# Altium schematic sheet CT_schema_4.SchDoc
size 357 x 184 mm
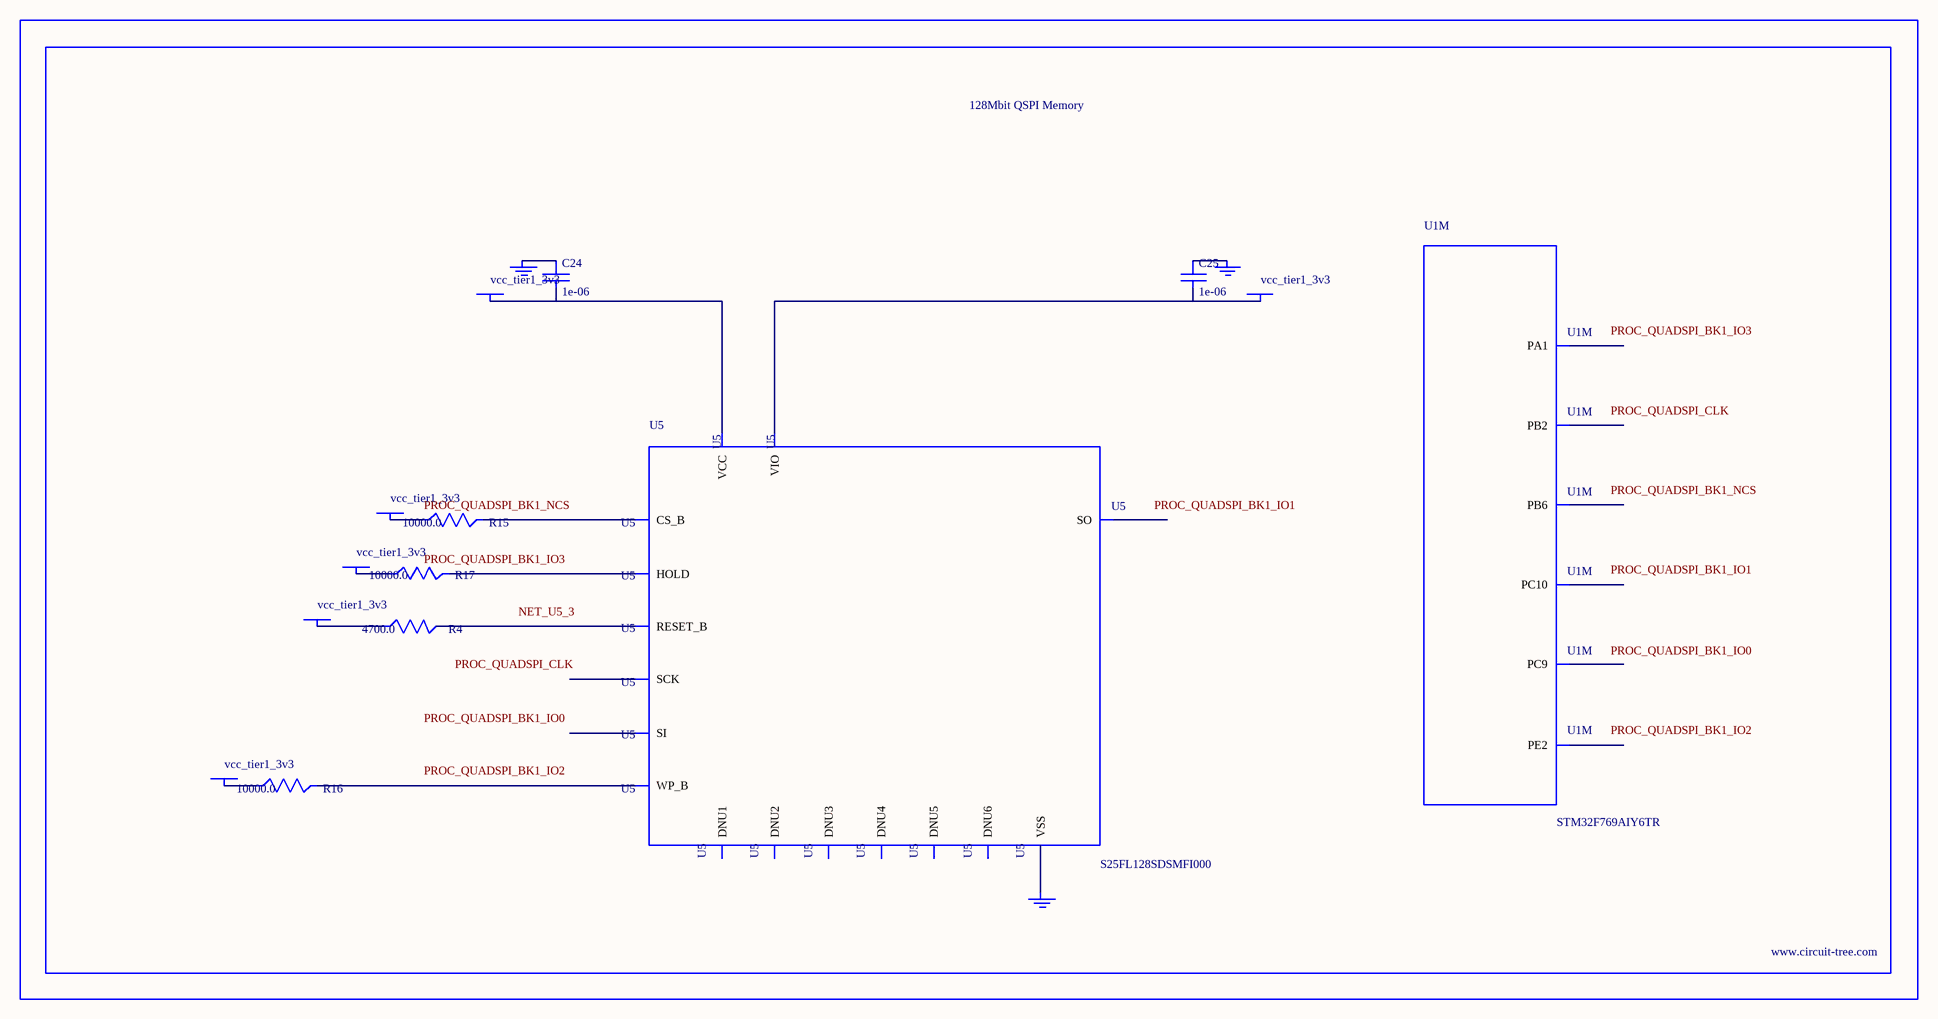
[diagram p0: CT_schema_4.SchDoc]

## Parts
BORDER3  (no value)
C24  1e-06  [C0603]
C25  1e-06  [C0603]
GND_INSTANCE_3_0  (no value)
GND_INSTANCE_3_1  (no value)
GND_INSTANCE_3_2  (no value)
POWER_INSTANCE_3_0  vcc_tier1_3v3
POWER_INSTANCE_3_1  vcc_tier1_3v3
POWER_INSTANCE_3_2  vcc_tier1_3v3
POWER_INSTANCE_3_3  vcc_tier1_3v3
POWER_INSTANCE_3_4  vcc_tier1_3v3
POWER_INSTANCE_3_5  vcc_tier1_3v3
R4  4700.0  [R0603]
R15  10000.0  [R0603]
R16  10000.0  [R0603]
R17  10000.0  [R0603]
U1  STM32F769AIY6TR  [WLCSP180]  (part M of 15)
U5  S25FL128SDSMFI000  [S25FL128SDSMFI000]

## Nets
NetC24_1: C24.1 GND_INSTANCE_3_0.0(GND)
NetC24_2: C24.2 POWER_INSTANCE_3_1.0(PWR) U5.2(VCC)
NetC25_1: C25.1 GND_INSTANCE_3_1.0(GND)
NetC25_2: C25.2 POWER_INSTANCE_3_4.0(PWR) U5.14(VIO)
NetGND_INSTANCE_3_2_0: GND_INSTANCE_3_2.0(GND) U5.10(VSS)
NetPOWER_INSTANCE_3_0_0: POWER_INSTANCE_3_0.0(PWR) R17.1
NetPOWER_INSTANCE_3_2_0: POWER_INSTANCE_3_2.0(PWR) R15.1
NetPOWER_INSTANCE_3_3_0: POWER_INSTANCE_3_3.0(PWR) R16.1
NetPOWER_INSTANCE_3_5_0: POWER_INSTANCE_3_5.0(PWR) R4.1
NetR4_2: R4.2 U5.3(RESET_B)
NetR15_2: R15.2 U5.7(CS_B)
NetR16_2: R16.2 U5.9(WP_B)
NetR17_2: R17.2 U5.1(HOLD)

Not connected (* = marked no-connect by the designer): U1 B4(PC10) B9(PB6) E1(PC9) E10(PE2) J7(PB2) J11(PA1); U5 4(DNU1) 5(DNU2) 6(DNU6) 8(SO) 11(DNU3) 12(DNU4) 13(DNU5) 15(SI) 16(SCK)

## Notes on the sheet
- Labels drawn without touching a wire or pin: NET_U5_3, PROC_QUADSPI_BK1_IO0, PROC_QUADSPI_BK1_IO1, PROC_QUADSPI_BK1_IO2, PROC_QUADSPI_BK1_IO3, PROC_QUADSPI_BK1_NCS, PROC_QUADSPI_CLK

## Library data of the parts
BORDER3 = BORDER_PAGE3
C24 C25 = C0603C105K3RACTU
GND_INSTANCE_3_0-GND_INSTANCE_3_2 = GND
POWER_INSTANCE_3_0-POWER_INSTANCE_3_5 = PWR
R4 = RC0603JR-074K7L
R15-R17 = RC0603JR-0710KL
